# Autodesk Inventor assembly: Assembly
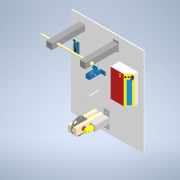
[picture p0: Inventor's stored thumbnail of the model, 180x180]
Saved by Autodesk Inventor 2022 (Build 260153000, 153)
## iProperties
Created: 2021-07
Part Number: Assembly
Document SubType Name: Assembly
Designer: Chimms
Author: Chimms
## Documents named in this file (17)
- C:\Users\Chimms\Documents\New folder (2)\FinalAssembly.iam
- C:\Users\Chimms\Documents\New folder (2)\base.ipt
- C:\Users\Chimms\Documents\New folder (2)\spool_pole.ipt
- C:\Users\Chimms\Documents\New folder (2)\bearing_final.ipt
- C:\Users\Chimms\Documents\New folder (2)\pulley_with_rod_winded side.ipt
- C:\Users\Chimms\Documents\New folder (2)\winding_spool.ipt
- C:\Users\Chimms\Documents\New folder (2)\motor_Mount.ipt
- C:\Users\Chimms\Documents\New folder (2)\motor.iam
- C:\Users\Chimms\Documents\New folder (2)\sensor_and_release_pulley_support.ipt
- C:\Users\Chimms\Documents\New folder (2)\looped_rod.ipt
- C:\Users\Chimms\Documents\New folder (2)\supportrod.ipt
- C:\Users\Chimms\Documents\New folder (2)\release_pulley.ipt
- C:\Users\Chimms\Documents\New folder (2)\arduino.ipt
- C:\Users\Chimms\Documents\New folder (2)\user_interface.ipt
- C:\Users\Chimms\Documents\New folder (2)\vertical_pole_release_movable.ipt
- C:\Users\Chimms\Documents\New folder (2)\vertical_pole_release_fixed.ipt
- C:\Users\Chimms\Documents\New folder (2)\unwinded_ribbon_rod.ipt
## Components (18 placed, 16 different names)
1. base:1 — Rigid:1, Rigid:2, Rigid:3, Rigid:5, Rigid:6, Rigid:7, Rigid:8, Rigid:9, Rigid:10
2. spool_pole:1 — Rigid:1, Rotational:1
3. spool_pole:2 — Rigid:2, Rotational:2, Rotational:4
4. bearing_final:1 — Rotational:1
5. bearing_final:2 — Rotational:2, Rotational:3
6. pulley_with_rod_winded side:1 — Rotational:3
7. winding_spool:1 — Rotational:4
8. motor_Mount:1 — Rigid:3, Rigid:4
9. motor:1 [sub-assembly] — Rigid:4
10. sensor_and_release_pulley_support:1 — Rigid:5, Rotational:5, Rotational:6
11. looped_rod:1 — Rigid:6
12. supportrod:1 — Rotational:5
13. release_pulley:1 — Rotational:6
14. arduino:1 — Rigid:7
15. user_interface:1 — Rigid:8
16. vertical_pole_release_movable:1 — Rigid:10
17. vertical_pole_release_fixed:1 — Rigid:9, Rotational:7
18. unwinded_ribbon_rod:1 — Rotational:7
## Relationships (17: WeldJoint 10, RevoluteJoint 7)
- Rigid:1 [WeldJoint]: base:1 ↔ spool_pole:1
- Rigid:2 [WeldJoint]: base:1 ↔ spool_pole:2
- Rotational:1 [RevoluteJoint]: spool_pole:1 ↔ bearing_final:1
- Rotational:2 [RevoluteJoint]: spool_pole:2 ↔ bearing_final:2
- Rotational:3 [RevoluteJoint]: bearing_final:2 ↔ pulley_with_rod_winded side:1
- Rotational:4 [RevoluteJoint]: spool_pole:2 ↔ winding_spool:1
- Rigid:3 [WeldJoint]: base:1 ↔ motor_Mount:1
- Rigid:4 [WeldJoint]: motor_Mount:1 ↔ motor:1
- Rigid:5 [WeldJoint]: base:1 ↔ sensor_and_release_pulley_support:1
- Rigid:6 [WeldJoint]: base:1 ↔ looped_rod:1
- Rotational:5 [RevoluteJoint]: sensor_and_release_pulley_support:1 ↔ supportrod:1
- Rotational:6 [RevoluteJoint]: sensor_and_release_pulley_support:1 ↔ release_pulley:1
- Rigid:7 [WeldJoint]: base:1 ↔ arduino:1
- Rigid:8 [WeldJoint]: base:1 ↔ user_interface:1
- Rigid:9 [WeldJoint]: base:1 ↔ vertical_pole_release_fixed:1
- Rigid:10 [WeldJoint]: base:1 ↔ vertical_pole_release_movable:1
- Rotational:7 [RevoluteJoint]: vertical_pole_release_fixed:1 ↔ unwinded_ribbon_rod:1
